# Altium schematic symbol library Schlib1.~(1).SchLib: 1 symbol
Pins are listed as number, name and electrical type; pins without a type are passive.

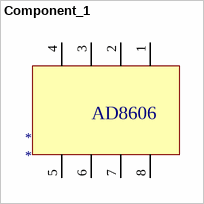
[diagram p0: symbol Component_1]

## Component_1
designator *
pins: 1 (power), 2 (power), 3 (power), 4 (power), 5 (power), 6 (power), 7 (power), 8 (power)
